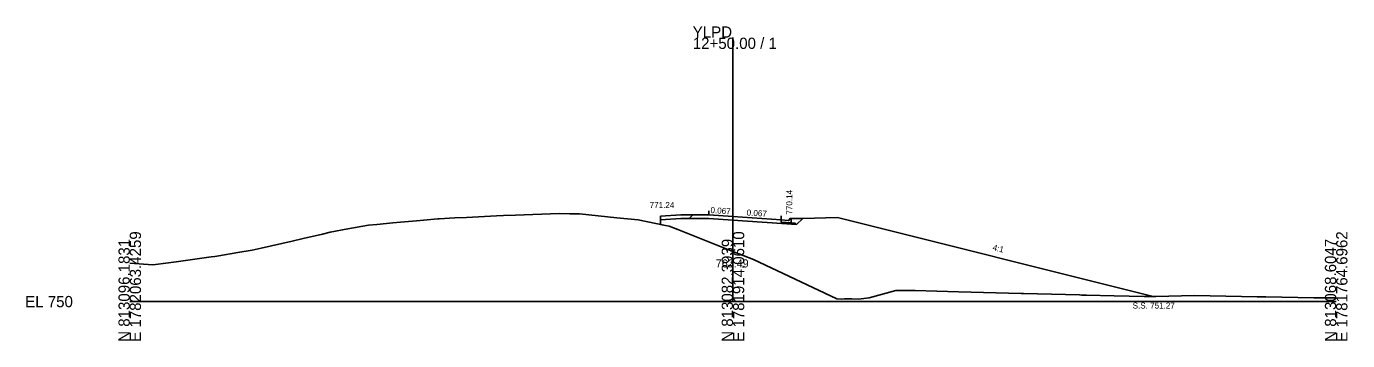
# Model space of a CAD drawing. Extents: x -26 to 353, y -10 to 9080.
# Drawn here: x -25.7 to 302.8, y 2490.3 to 2568.4 of the extents above; entities that cross this region are included whole.
import ezdxf

# ---------------------------------------------------------------- set-up
doc = ezdxf.new("R2010")
doc.units = 0
for name, color, linetype in [('Exist Cross Section Cell', 7, 'Continuous'), ('Exist XS Center Line Elevation Label', 7, 'Continuous'), ('Exist XS Ground Line', 7, 'Continuous'), ('Prop XS Dump Level', 7, 'Continuous'), ('Prop XS Earthwork Shape', 7, 'Continuous'), ('Prop XS EOT Tick Mark', 7, 'Continuous'), ('Prop XS Finish Grade', 7, 'Continuous'), ('Prop XS Finish Grade CurbGutter', 7, 'Continuous'), ('Prop XS Finish Grade Earthwork', 7, 'Continuous'), ('Prop XS Finish Grade Paved Shoulder', 7, 'Continuous'), ('Prop XS Finish Grade Pavement', 7, 'Continuous'), ('Prop XS Hydro Elevations', 7, 'Continuous'), ('Prop XS Pvmt Edge Slope', 7, 'Continuous'), ('Prop XS SE Text', 7, 'Continuous'), ('Prop XS Side Slope Text', 7, 'Continuous'), ('Prop XS SS Elevation Text', 7, 'Continuous'), ('Prop XS Subgrade CurbGutter', 7, 'Continuous'), ('Prop XS Subgrade Earthwork', 7, 'Continuous'), ('Scratch_Level_3', 7, 'Continuous')]:
    doc.layers.add(name, color=color, linetype=linetype)

msp = doc.modelspace()

# ---------------------------------------------------------------- linework, layer by layer
at = {"layer": 'Exist Cross Section Cell'}
for p, q in [((150, 2500), (150, 2565.64)), ((0, 2500), (150, 2500)), ((150, 2500), (300, 2500))]:
    msp.add_line(p, q, dxfattribs=at)
at = {"layer": 'Exist XS Ground Line'}
for p, q in [((67.3, 2519.74), (71.32, 2520.09)), ((71.32, 2520.09), (76.6, 2520.56)), ((76.6, 2520.56), (76.95, 2520.58)), ((76.95, 2520.58), (80.87, 2520.81)), ((80.87, 2520.81), (83.78, 2520.95)), ((83.78, 2520.95), (91.22, 2521.32)), ((91.22, 2521.32), (92.97, 2521.4)), ((92.97, 2521.4), (95.96, 2521.5)), ((95.96, 2521.5), (106.82, 2521.88)), ((106.82, 2521.88), (109.46, 2521.85)), ((109.46, 2521.85), (111.82, 2521.83)), ((111.82, 2521.83), (121.09, 2520.86)), ((121.09, 2520.86), (126.47, 2520.35)), ((126.47, 2520.35), (133.22, 2518.94)), ((43.1, 2515.7), (47.91, 2516.78)), ((47.91, 2516.78), (49.87, 2517.26)), ((49.87, 2517.26), (54.2, 2518.06)), ((54.2, 2518.06), (59.35, 2519)), ((59.35, 2519), (61.44, 2519.2)), ((61.44, 2519.2), (65.44, 2519.57)), ((65.44, 2519.57), (67.3, 2519.74)), ((133.22, 2518.94), (134.14, 2518.72)), ((134.14, 2518.72), (136.26, 2517.96)), ((136.26, 2517.96), (137.51, 2517.46)), ((137.51, 2517.46), (150, 2512.49)), ((31.18, 2512.96), (32.72, 2513.31)), ((32.72, 2513.31), (40.35, 2515.04)), ((40.35, 2515.04), (43.1, 2515.7)), ((11.54, 2509.92), (20.25, 2511.15)), ((20.25, 2511.15), (21.2, 2511.22)), ((21.2, 2511.22), (22.15, 2511.35)), ((22.15, 2511.35), (26.92, 2512.18)), ((26.92, 2512.18), (30.47, 2512.8)), ((30.47, 2512.8), (31.18, 2512.96)), ((150, 2512.49), (155.12, 2510.45)), ((155.12, 2510.45), (175.84, 2500.67)), ((0, 2509.55), (5.78, 2509.14)), ((5.78, 2509.14), (6.38, 2509.22)), ((6.38, 2509.22), (11.54, 2509.92)), ((175.84, 2500.67), (177.06, 2500.57)), ((177.06, 2500.57), (177.77, 2500.72)), ((177.77, 2500.72), (179.58, 2500.7)), ((179.58, 2500.7), (181.24, 2500.63)), ((181.24, 2500.63), (183.9, 2500.96)), ((183.9, 2500.96), (190.54, 2502.78)), ((190.54, 2502.78), (195.29, 2502.73)), ((195.29, 2502.73), (206.07, 2502.41)), ((206.07, 2502.41), (221.64, 2502)), ((221.64, 2502), (222.21, 2502)), ((222.21, 2502), (236.2, 2501.65)), ((236.2, 2501.65), (236.66, 2501.64)), ((236.66, 2501.64), (237.94, 2501.58)), ((237.94, 2501.58), (244.76, 2501.4)), ((244.76, 2501.4), (252.29, 2501.3)), ((252.29, 2501.3), (255.2, 2501.25)), ((255.2, 2501.25), (264.74, 2501.48)), ((264.74, 2501.48), (280.39, 2501.22)), ((280.39, 2501.22), (281.48, 2501.21)), ((281.48, 2501.21), (281.93, 2501.22)), ((281.93, 2501.22), (282.53, 2501.2)), ((282.53, 2501.2), (294.48, 2500.91)), ((294.48, 2500.91), (300, 2500.95))]:
    msp.add_line(p, q, dxfattribs=at)
at = {"layer": 'Prop XS Dump Level'}
for p, q in [((144, 2521.56), (150, 2521.16)), ((150, 2521.16), (162, 2520.36))]:
    msp.add_line(p, q, dxfattribs=at)
at = {"layer": 'Prop XS Earthwork Shape'}
msp.add_lwpolyline([(132, 2519.19), (133.22, 2518.94), (134.14, 2518.72), (136.26, 2517.96), (137.51, 2517.46), (150, 2512.49), (155.12, 2510.45), (175.84, 2500.67), (177.06, 2500.57), (177.77, 2500.72), (179.58, 2500.7), (181.24, 2500.63), (183.9, 2500.96), (190.54, 2502.78), (195.29, 2502.73), (206.07, 2502.41), (221.64, 2502), (222.21, 2502), (236.2, 2501.65), (236.66, 2501.64), (237.94, 2501.58), (244.76, 2501.4), (252.29, 2501.3), (254.47, 2501.27), (176, 2520.88), (167.36, 2520.7), (165.84, 2519.18), (149.94, 2520.24), (143.97, 2520.64), (139.09, 2520.67), (137.03, 2520.69), (132, 2520.32)], close=True, dxfattribs=at)
at = {"layer": 'Prop XS EOT Tick Mark'}
for p, q in [((144, 2521.56), (144, 2522.56)), ((162, 2520.36), (162, 2521.36))]:
    msp.add_line(p, q, dxfattribs=at)
at = {"layer": 'Prop XS Finish Grade'}
for p, q in [((137, 2521.61), (132, 2521.24)), ((132, 2521.24), (132, 2520.32)), ((140, 2521.59), (137, 2521.61)), ((164.5, 2520.64), (167.36, 2520.7))]:
    msp.add_line(p, q, dxfattribs=at)
at = {"layer": 'Prop XS Finish Grade CurbGutter'}
for p, q in [((162, 2520.36), (163.75, 2520.17)), ((163.75, 2520.17), (163.87, 2520.19)), ((163.87, 2520.19), (163.97, 2520.29)), ((163.97, 2520.29), (164.03, 2520.54)), ((164.03, 2520.54), (164.12, 2520.63)), ((164.25, 2520.64), (164.12, 2520.63)), ((164.5, 2520.64), (164.25, 2520.64))]:
    msp.add_line(p, q, dxfattribs=at)
at = {"layer": 'Prop XS Finish Grade Earthwork'}
for p, q in [((132, 2520.32), (132, 2519.19)), ((167.36, 2520.7), (176, 2520.88)), ((176, 2520.88), (254.47, 2501.27))]:
    msp.add_line(p, q, dxfattribs=at)
at = {"layer": 'Prop XS Finish Grade Paved Shoulder'}
msp.add_line((144, 2521.56), (140, 2521.59), dxfattribs=at)
at = {"layer": 'Prop XS Finish Grade Pavement'}
for p, q in [((144, 2521.56), (150, 2521.16)), ((150, 2521.16), (162, 2520.36))]:
    msp.add_line(p, q, dxfattribs=at)
at = {"layer": 'Prop XS Pvmt Edge Slope'}
for p, q in [((140, 2521.59), (139.09, 2520.67)), ((164.5, 2519.61), (165.5, 2519.54)), ((165.5, 2519.54), (165.84, 2519.18))]:
    msp.add_line(p, q, dxfattribs=at)
at = {"layer": 'Prop XS Subgrade CurbGutter'}
for p, q in [((162, 2520.36), (162, 2519.78)), ((164.5, 2519.61), (164.5, 2520.64)), ((162, 2519.78), (164.5, 2519.61))]:
    msp.add_line(p, q, dxfattribs=at)
at = {"layer": 'Prop XS Subgrade Earthwork'}
for p, q in [((137.03, 2520.69), (132, 2520.32)), ((139.09, 2520.67), (137.03, 2520.69)), ((143.97, 2520.64), (139.09, 2520.67)), ((143.97, 2520.64), (149.94, 2520.24)), ((149.94, 2520.24), (165.84, 2519.18)), ((165.84, 2519.18), (167.36, 2520.7))]:
    msp.add_line(p, q, dxfattribs=at)
at = {"layer": 'Scratch_Level_3'}
for p, q in [((137, 2521.61), (132, 2521.24)), ((132, 2521.24), (132, 2520.32)), ((132, 2520.32), (137.03, 2520.69)), ((140, 2521.59), (137, 2521.61)), ((137.03, 2520.69), (139.09, 2520.67)), ((139.09, 2520.67), (140, 2521.59))]:
    msp.add_line(p, q, dxfattribs=at)

# ---------------------------------------------------------------- texts
at = {"layer": 'Exist Cross Section Cell'}
for s, p in [('YLPD', (140, 2565.64)), ('12+50.00 / 1', (140, 2562.84)), ('EL 750', (-26, 2498.6))]:
    msp.add_text(s, height=2.8, dxfattribs=at).set_placement(p)
for s, p in [('E 1782063.4259', (2.8, 2490)), ('E 1781914.0610', (152.8, 2490)), ('E 1781764.6962', (302.8, 2490)), ('N 813096.1831', (0, 2490)), ('N 813082.3939', (150, 2490)), ('N 813068.6047', (300, 2490))]:
    msp.add_text(s, height=2.8, rotation=90, dxfattribs=at).set_placement(p)
at = {"layer": 'Exist XS Center Line Elevation Label'}
msp.add_text('762.49', height=2, dxfattribs=at).set_placement((145.73, 2508.49))
at = {"layer": 'Prop XS Dump Level'}
msp.add_text('Case4', height=0.04, dxfattribs=at).set_placement((132, 2521.2))
at = {"layer": 'Prop XS Hydro Elevations'}
msp.add_text('770.14', height=1.5, rotation=90, dxfattribs=at).set_placement((164.75, 2521.64))
at = {"layer": 'Prop XS SE Text'}
for rotation, p in [(356.1845, (144.37, 2522.03)), (356.1851, (153.37, 2521.43))]:
    msp.add_text('0.067', height=1.5, rotation=rotation, dxfattribs=at).set_placement(p)
at = {"layer": 'Prop XS Side Slope Text'}
msp.add_text('4:1', height=1.5, rotation=345.9638, dxfattribs=at).set_placement((214.45, 2512.82))
at = {"layer": 'Prop XS SS Elevation Text'}
for s, p in [('771.24', (129.29, 2523.26)), ('S.S. 751.27', (249.39, 2498.27))]:
    msp.add_text(s, height=1.5, dxfattribs=at).set_placement(p)

doc.saveas('drawing.dxf')
